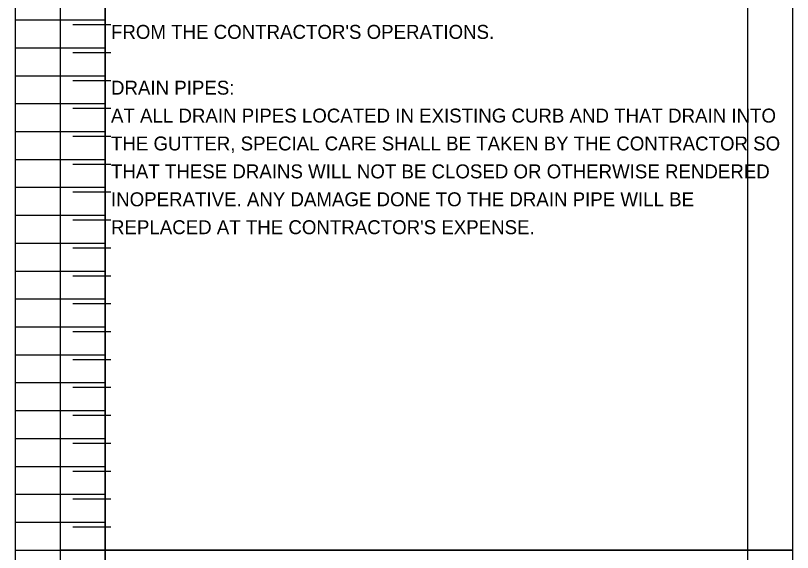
# Model space of a CAD drawing. Extents: x 12316 to 12541, y 1124 to 1850.
# Drawn here: x 12521.92 to 12529.71, y 1789.29 to 1794.68 of the extents above; entities that cross this region are included whole.
import ezdxf

# ---------------------------------------------------------------- set-up
doc = ezdxf.new("R2010")
doc.units = 0
doc.layers.add('SC_Scratch1', color=7, linetype='Continuous')
doc.layers.add('SH_Data', color=7, linetype='Continuous')

msp = doc.modelspace()

# ---------------------------------------------------------------- linework, layer by layer
at = {"layer": 'SC_Scratch1'}
for p, q in [((12521.9194, 1789.3113), (12521.9194, 1809.4713)), ((12522.8194, 1789.3113), (12522.8194, 1809.4713)), ((12522.8194, 1789.3113), (12522.8194, 1809.4713)), ((12522.8194, 1809.4713), (12522.8194, 1789.3113)), ((12529.2594, 1809.4713), (12529.2594, 1789.3113)), ((12521.9194, 1794.6313), (12522.8194, 1794.6313)), ((12522.8764, 1794.5812), (12522.4923, 1794.5812)), ((12521.9194, 1794.3513), (12522.8194, 1794.3513)), ((12522.8764, 1794.3012), (12522.4923, 1794.3012)), ((12521.9194, 1794.0713), (12522.8194, 1794.0713)), ((12522.8764, 1794.0212), (12522.4923, 1794.0212)), ((12521.9194, 1793.7913), (12522.8194, 1793.7913)), ((12522.8764, 1793.7412), (12522.4923, 1793.7412)), ((12521.9194, 1793.5113), (12522.8194, 1793.5113)), ((12522.8764, 1793.4612), (12522.4923, 1793.4612)), ((12521.9194, 1793.2313), (12522.8194, 1793.2313)), ((12522.8764, 1793.1812), (12522.4923, 1793.1812)), ((12521.9194, 1792.9513), (12522.8194, 1792.9513)), ((12522.8764, 1792.9012), (12522.4923, 1792.9012)), ((12521.9194, 1792.6713), (12522.8194, 1792.6713)), ((12522.8764, 1792.6212), (12522.4923, 1792.6212)), ((12521.9194, 1792.3913), (12522.8194, 1792.3913)), ((12522.8764, 1792.3412), (12522.4923, 1792.3412)), ((12521.9194, 1792.1113), (12522.8194, 1792.1113)), ((12522.8764, 1792.0612), (12522.4923, 1792.0612)), ((12521.9194, 1791.8313), (12522.8194, 1791.8313)), ((12522.8764, 1791.7812), (12522.4923, 1791.7812)), ((12521.9194, 1791.5513), (12522.8194, 1791.5513)), ((12522.8764, 1791.5012), (12522.4923, 1791.5012)), ((12521.9194, 1791.2713), (12522.8194, 1791.2713)), ((12522.8764, 1791.2212), (12522.4923, 1791.2212)), ((12521.9194, 1790.9913), (12522.8194, 1790.9913)), ((12522.8764, 1790.9412), (12522.4923, 1790.9412)), ((12521.9194, 1790.7113), (12522.8194, 1790.7113)), ((12522.8764, 1790.6612), (12522.4923, 1790.6612)), ((12521.9194, 1790.4313), (12522.8194, 1790.4313)), ((12522.8764, 1790.3812), (12522.4923, 1790.3812)), ((12521.9194, 1790.1513), (12522.8194, 1790.1513)), ((12522.8764, 1790.1012), (12522.4923, 1790.1012)), ((12521.9194, 1789.8713), (12522.8194, 1789.8713)), ((12522.8764, 1789.8212), (12522.4923, 1789.8212)), ((12521.9194, 1789.5913), (12522.8194, 1789.5913)), ((12522.8764, 1789.5412), (12522.4923, 1789.5412)), ((12521.9194, 1789.3113), (12522.8194, 1789.3113)), ((12521.9194, 1769.1513), (12521.9194, 1789.3113)), ((12521.9194, 1789.3113), (12522.8194, 1789.3113)), ((12522.8194, 1769.1513), (12522.8194, 1789.3113)), ((12529.2594, 1789.3113), (12522.8194, 1789.3113)), ((12522.8194, 1789.3113), (12522.8194, 1769.1513))]:
    msp.add_line(p, q, dxfattribs=at)
for points in [[(12522.3694, 1809.4713), (12529.7094, 1809.4713), (12529.7094, 1789.3113), (12522.3694, 1789.3113)], [(12522.3694, 1789.3113), (12529.7094, 1789.3113), (12529.7094, 1769.1513), (12522.3694, 1769.1513)], [(12522.8194, 1789.3113), (12529.2594, 1789.3113), (12529.2594, 1769.1513), (12522.8194, 1769.1513)]]:
    msp.add_lwpolyline(points, close=True, dxfattribs=at)

# ---------------------------------------------------------------- texts
at = {"layer": 'SH_Data'}
for s, p in [("FROM THE CONTRACTOR'S OPERATIONS.", (12522.8764, 1794.4412)), ('DRAIN PIPES:', (12522.8764, 1793.8812)), ('AT ALL DRAIN PIPES LOCATED IN EXISTING CURB AND THAT DRAIN INTO ', (12522.8764, 1793.6012)), ('THE GUTTER, SPECIAL CARE SHALL BE TAKEN BY THE CONTRACTOR SO ', (12522.8764, 1793.3212)), ('THAT THESE DRAINS WILL NOT BE CLOSED OR OTHERWISE RENDERED ', (12522.8764, 1793.0412)), ('INOPERATIVE. ANY DAMAGE DONE TO THE DRAIN PIPE WILL BE ', (12522.8764, 1792.7612)), ("REPLACED AT THE CONTRACTOR'S EXPENSE.", (12522.8764, 1792.4812))]:
    msp.add_text(s, height=0.14, dxfattribs=at).set_placement(p)

doc.saveas('drawing.dxf')
